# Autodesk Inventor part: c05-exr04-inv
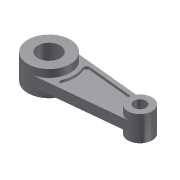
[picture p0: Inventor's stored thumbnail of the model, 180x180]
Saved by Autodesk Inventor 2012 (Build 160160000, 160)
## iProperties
Created: 2009-09
Part Number: c05-exr04-inv
Document SubType Name: Modeling
Designer: Sham
Density: 1 g/cm^3
Material: Default
Author: Sham
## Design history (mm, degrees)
sketch "Sketch1"
  geometry: C1 r 21 at (-31, 0); C2 r 11 at (-31, 0); C3 r 6 at (59, 0); C4 r 12 at (59, 0)
  constraints: 4 centre point, 1 coincident, 1 concentric
  dimensions: "d0" = 42 diameter of C1; "d1" = 22 diameter of C2; "d2" = 12 diameter of C3; "d3" = 24 diameter of C4; "d4" = 90 distance of C3.centre C1.centre
extrude "Extrusion1" new body sketch "Sketch1" stored distance "d5" = 25; taper "d6" = 0 deg
sketch "Sketch3"
  geometry: L1 (-28.805, 20.895)-(60.295, 11.939); L2 (-28.805, -20.895)-(60.295, -11.94); A1 r 21 centre (-30.905, 0) between (-28.805, -20.895) and (-28.805, 20.895); A2 r 12 centre (59.095, 0) between (60.295, 11.939) and (60.295, -11.94); 1 further point
  constraints: 5 end point, 5 point on circle, 4 tangent, 2 centre point, 1 point on line, 1 other
  dimensions: "d7" = 42 diameter of A1; "d9" = 0 vertical distance of point (0, 0) A1.centre; "d10" = 24 diameter of A2; "d11" = 90 distance of A1.centre A2.centre
extrude "Extrusion2" join sketch "Sketch3" stored distance "d12" = 10; taper "d13" = 0 deg
sketch "Sketch6"
  geometry: L1 (-28.805, 20.895)-(60.295, 11.939) reference; L2 (60.295, -11.94)-(-28.805, -20.895) reference; L3 (-5.078, 14.49)-(42.919, 9.666); L4 (-5.078, -14.49)-(42.919, -9.666); A1 r 12 centre (59, 0) between (59.091, 12) and (59.004, -12) reference; A2 r 21 centre (-30.905, 0) between (-28.805, -20.895) and (-28.805, 20.895) reference; A3 r 16 centre (59, 0) between (44.528, 6.823) and (44.528, -6.823); A4 r 25 centre (-30.905, 0) between (-8.113, -10.272) and (-8.113, 10.272); A5 r 3 centre (-5.378, 11.505) between (-5.078, 14.49) and (-8.113, 10.272); A6 r 3 centre (-5.378, -11.505) between (-8.113, -10.272) and (-5.078, -14.49); A7 r 2 centre (42.719, 7.676) between (44.528, 6.823) and (42.919, 9.666); A8 r 2 centre (42.719, -7.676) between (42.919, -9.666) and (44.528, -6.823); 4 further points
  constraints: 16 point on circle, 8 tangent, 6 centre point, 4 end point, 4 point on line, 2 coincident, 2 parallel
  dimensions: "d16" = 4 distance between parallel lines of L3 L1; "d17" = 4 distance between parallel lines of L2 L4; "d18" = 50 diameter of A4; "d19" = 32 diameter of A3; "d20" = 3 radius of A5; "d21" = 3 radius of A6; "d22" = 2 radius of A7; "d23" = 2 radius of A8
extrude "Extrusion3" cut sketch "Sketch6" distance "d24" = 2.5; taper "d25" = 0 deg
sketch "Sketch10"
  geometry: L1 (5.078, -14.49)-(-42.919, -9.666) reference; L2 (-42.919, 9.666)-(5.078, 14.49) reference; A1 r 3 centre (5.378, -11.505) between (5.078, -14.49) and (8.113, -10.272) reference; A2 r 25 centre (30.905, 0) between (8.113, 10.272) and (8.113, -10.272) reference; A3 r 3 centre (5.378, 11.505) between (8.113, 10.272) and (5.078, 14.49) reference; A4 r 2 centre (-42.719, 7.676) between (-42.919, 9.666) and (-44.528, 6.823) reference; A5 r 16 centre (-59, 0) between (-44.528, -6.823) and (-44.528, 6.823) reference; A6 r 2 centre (-42.719, -7.676) between (-44.528, -6.823) and (-42.919, -9.666) reference
extrude "Extrusion4" cut sketch "Sketch10" distance "d26" = 2.5; taper "d27" = 0 deg
body "Solid1"
